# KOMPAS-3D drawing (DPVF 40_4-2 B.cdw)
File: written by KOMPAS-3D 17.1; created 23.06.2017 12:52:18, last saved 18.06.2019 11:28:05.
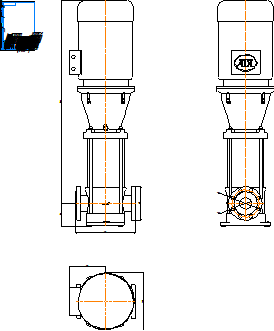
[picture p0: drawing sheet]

Sheet 1: A4, portrait

Title block, sheet 1: name: DPVF 40_4-2 B; material: Внимание! Данный продукт является объектом авторского права ООО «Торговый Дом АДЛ». / Запрещается изменение, копирование, распространение / (в том числе путем копирования на другие сайты и ресурсы в Интернете) / или любое иное использование информации и объектов без предварительного / согласия правообладателя (ООО «Торговый Дом АДЛ»).; scale: 1:1; sheets: 1; organisation: ООО "Торговый дом АДЛ"; sheet format: A4; stored path: C:\Клочков АВ\Насосы\DP PAMS\DPVF 40\Компас 2d\DPVF 40_4-2 B.cdw

Views: Спереди 1
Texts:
  Клочков АВ
  ООО АДЛ ГРУПП
Dimensions and other numbers on the sheet: 365; 223; 350; 209,6; 1234,5; 140; 168,1; 76,2; 1:1; 1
